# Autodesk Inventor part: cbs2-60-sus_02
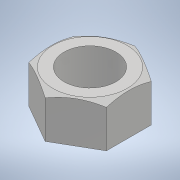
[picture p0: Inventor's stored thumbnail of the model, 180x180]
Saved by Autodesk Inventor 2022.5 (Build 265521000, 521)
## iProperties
Part Number: cbs2-60-sus_02
Material: 一般
Document SubType Name: Modeling
Designer: ImaoCorp
Density: 1 g/cm^3
Appearance: 既定
Author: ImaoCorp
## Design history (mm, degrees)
feature "cbs2-60-sus_02"
node "ソリッド1"
